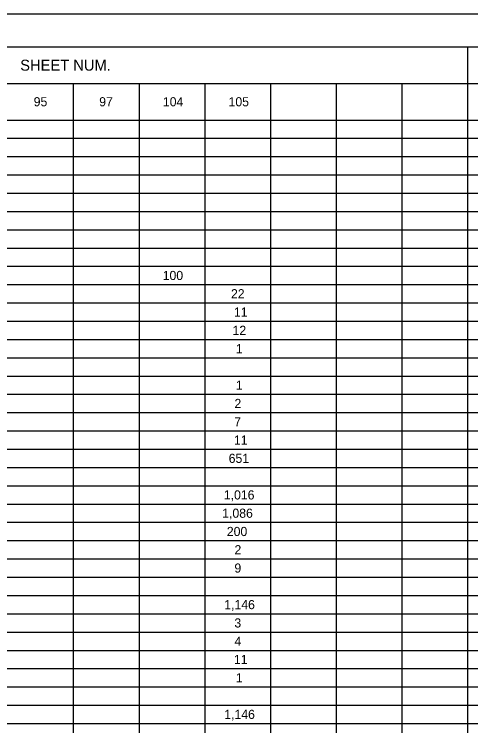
# Model space of a CAD drawing. Extents: x 0 to 76.3, y 0 to 22.
# Drawn here: x 6.62 to 13.61, y 11.1 to 22 of the extents above; entities that cross this region are included whole.
import ezdxf

# ---------------------------------------------------------------- set-up
doc = ezdxf.new("R2010")
doc.units = 0
for name, color, linetype in [('Default', 7, 'Continuous'), ('SH_Border', 7, 'Continuous'), ('SH_Cut_Line', 7, 'Continuous')]:
    doc.layers.add(name, color=color, linetype=linetype)

msp = doc.modelspace()

# ---------------------------------------------------------------- linework, layer by layer
at = {"layer": 'Default'}
for p, q in [((1.5, 21.5), (32.004, 21.5)), ((13.556, 21.5), (13.556, 0.5)), ((1.5, 20.94), (15.566, 20.94)), ((7.528, 20.94), (7.528, 0.5)), ((8.533, 20.94), (8.533, 0.5)), ((9.538, 20.94), (9.538, 0.5)), ((10.542, 20.94), (10.542, 0.5)), ((11.547, 20.94), (11.547, 0.5)), ((12.552, 20.94), (12.552, 0.5)), ((1.5, 20.38), (32.004, 20.38)), ((1.5, 20.1), (32.004, 20.1)), ((1.5, 19.82), (32.004, 19.82)), ((1.5, 19.54), (32.004, 19.54)), ((1.5, 19.26), (32.004, 19.26)), ((1.5, 18.98), (32.004, 18.98)), ((1.5, 18.7), (32.004, 18.7)), ((1.5, 18.42), (32.004, 18.42)), ((1.5, 18.14), (32.004, 18.14)), ((1.5, 17.86), (32.004, 17.86)), ((1.5, 17.58), (32.004, 17.58)), ((1.5, 17.3), (32.004, 17.3)), ((1.5, 17.02), (32.004, 17.02)), ((1.5, 16.74), (32.004, 16.74)), ((1.5, 16.46), (32.004, 16.46)), ((1.5, 16.18), (32.004, 16.18)), ((1.5, 15.9), (32.004, 15.9)), ((1.5, 15.62), (32.004, 15.62)), ((1.5, 15.34), (32.004, 15.34)), ((1.5, 15.06), (32.004, 15.06)), ((1.5, 14.78), (32.004, 14.78)), ((1.5, 14.5), (32.004, 14.5)), ((1.5, 14.22), (32.004, 14.22)), ((1.5, 13.94), (32.004, 13.94)), ((1.5, 13.66), (32.004, 13.66)), ((1.5, 13.38), (32.004, 13.38)), ((1.5, 13.1), (32.004, 13.1)), ((1.5, 12.82), (32.004, 12.82)), ((1.5, 12.54), (32.004, 12.54)), ((1.5, 12.26), (32.004, 12.26)), ((1.5, 11.98), (32.004, 11.98)), ((1.5, 11.7), (32.004, 11.7)), ((1.5, 11.42), (32.004, 11.42)), ((1.5, 11.14), (32.004, 11.14))]:
    msp.add_line(p, q, dxfattribs=at)
at = {"layer": 'SH_Border'}
msp.add_lwpolyline([(1.5, 21.5), (33.5, 21.5), (33.5, 0.5), (1.5, 0.5)], close=True, dxfattribs=at)
at = {"layer": 'SH_Cut_Line'}
msp.add_lwpolyline([(0, 0), (34, 0), (34, 22), (0, 22)], close=True, dxfattribs=at)

# ---------------------------------------------------------------- texts
at = {"layer": 'Default'}
for s, height, p in [('SHEET NUM.', 0.168, (6.716, 21.136)), ('95', 0.14, (6.922, 20.59)), ('97', 0.14, (7.924, 20.59)), ('104', 0.14, (8.898, 20.59)), ('105', 0.14, (9.902, 20.59)), ('100', 0.14, (8.895, 17.93)), ('22', 0.14, (9.939, 17.65)), ('11', 0.14, (9.984, 17.37)), ('12', 0.14, (9.963, 17.09)), ('1', 0.14, (10.014, 16.81)), ('1', 0.14, (10.014, 16.25)), ('2', 0.14, (9.993, 15.97)), ('7', 0.14, (9.989, 15.69)), ('11', 0.14, (9.984, 15.41)), ('651', 0.14, (9.904, 15.13)), ('1,016', 0.14, (9.83, 14.57)), ('1,086', 0.14, (9.805, 14.29)), ('200', 0.14, (9.876, 14.01)), ('2', 0.14, (9.993, 13.73)), ('9', 0.14, (9.992, 13.45)), ('1,146', 0.14, (9.836, 12.89)), ('3', 0.14, (9.991, 12.61)), ('4', 0.14, (9.993, 12.33)), ('11', 0.14, (9.984, 12.05)), ('1', 0.14, (10.014, 11.77)), ('1,146', 0.14, (9.836, 11.21))]:
    msp.add_text(s, height=height, dxfattribs=at).set_placement(p)

doc.saveas('drawing.dxf')
